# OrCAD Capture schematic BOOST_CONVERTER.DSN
size A; title: Boost Converter; rev: 1
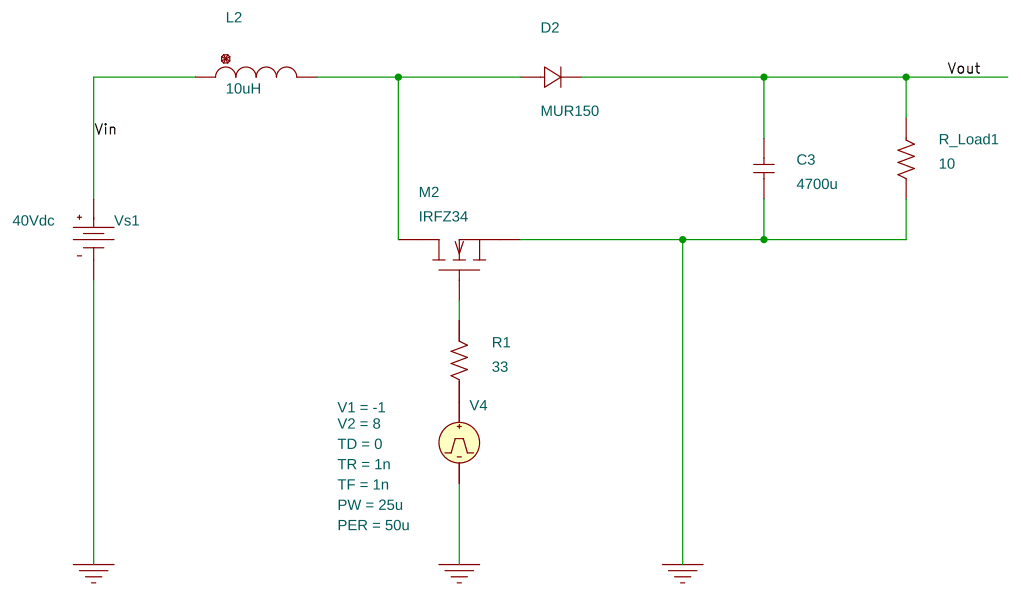
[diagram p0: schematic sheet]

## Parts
C3  4700u  [RAD/CK05]
D2  MUR150  [DO-41]
L2  10uH  [DISC/.350x.175/LS.200x.100/.034]
M2  IRFZ34  [TO220AB]
R1  33  [AX/RC05]
R_Load1  10  [AX/RC05]
V4  VPULSE
Vs1  VDC

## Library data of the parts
C3 = C: IC: 70
D2 = MUR150
L2 = L
M2 = IRFZ34
R1 R_Load1 = R
V4 = VPULSE: PER: 50u; PW: 25u; TD: 0; TF: 1n; TR: 1n; V1: -1; V2: 8
Vs1 = VDC: DC: 40Vdc

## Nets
Vin: L2.1 Vs1.0(+)
0: C3.2 M2.3(s) R_Load1.2 V4.2(-) Vs1.1(-)
Vout: C3.1 D2.2 R_Load1.1
N9022867: D2.1 L2.2 M2.2(d)
N9025597: M2.1(g) R1.2
N9028585: R1.1 V4.1(+)
